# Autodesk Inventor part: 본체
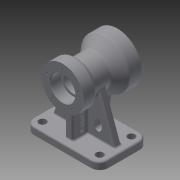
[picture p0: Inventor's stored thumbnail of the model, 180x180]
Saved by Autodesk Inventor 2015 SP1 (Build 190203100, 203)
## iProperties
Created: 2015-08
Part Number: 본체
Material: 일반
Document SubType Name: Modeling
Designer: jun
Density: 1 g/cm^3
Appearance: 기본값
Author: jun
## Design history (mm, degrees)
sketch "스케치1"
  geometry: L1 (-61, 40)-(61, 40); L2 (61, 40)-(61, -40); L3 (61, -40)-(-61, -40); L4 (-61, -40)-(-61, 40); L5 (-61, 40)-(61, -40); 2 further points
  constraints: 10 end point, 2 parallel, 1 coincident, 1 horizontal, 1 midpoint, 1 perpendicular
  dimensions: "d0" = 122 distance of L1.start L1.end; "d1" = 80 distance of L1.end L2.end
extrude "돌출1" new body sketch "스케치1" distance "d2" = 12; taper "d3" = 0 deg
sketch "스케치2"
  geometry: L1 (40, 12)-(40, 0) reference; L2 (40, 0)-(-40, 0) reference; L3 (-40, 0)-(-40, 12) reference; L4 (-40, 12)-(40, 12) reference; L5 (50, 90)-(-40, 90); L6 (50, 90)-(50, 49.861); L7 (50, 49.861)-(30, 49.861); L8 (-40, 90)-(-40, 55); L9 (-40, 55)-(-20, 55); L10 (30, 49.861)-(13.15, 64); L11 (13.15, 64)-(-14.804, 64); L12 (-14.804, 64)-(-20, 55); L13 (-40, 0)-(-40, 12) reference; 2 further points
  constraints: 16 end point, 2 horizontal, 2 perpendicular, 2 vertical, 1 midpoint, 1 vertical alignment
  dimensions: "d8" = 35 distance of L5.end L8.end; "d9" = 20 distance of L8.end L9.end; "d16" = 60 deg angle of L12 L11; "d103" = 90 distance of L5.start L5.end; "d106" = 90 distance between parallel lines of L2 L5; "d107" = 20 distance of L6.end L7.end; "d108" = 40 deg angle of L10 L11; "d109" = 26 distance between parallel lines of L5 L11; "d110" = 40.139 distance of L5.start L6.end
revolve "회전1" sketch "스케치2" stored, may be unused: angle "d17" = 90 deg
sketch "스케치3"
  geometry: L1 (61, 12)-(61, 0) reference; L2 (61, 0)-(-61, 0) reference; L3 (-61, 0)-(-61, 12) reference; L4 (-61, 12)-(61, 12) reference; L5 (-25.091, 83.185)-(-51, 12); L6 (-51, 12)-(51, 12); L7 (61, 12)-(-61, 12) reference; L8 (51, 12)-(25.091, 83.185); A1 r 26 centre (0, 90) between (-25.091, 83.185) and (25.091, 83.185) reference; A2 r 26 centre (0, 90) between (-25.091, 83.185) and (25.091, 83.185) reference; 1 further point
  constraints: 6 end point, 4 point on circle, 2 point on line
  dimensions: "d18" = 70 deg angle of L4 L8; "d19" = 70 deg angle of L4 L5; "d20" = 10 distance from line of L3 L5.end; "d21" = 10 distance from line of L1 L6.end
extrude "돌출2" join sketch "스케치3" stored distance "d22" = 12; taper "d23" = 0 deg
sketch "스케치4"
  geometry: L1 (40, 12)-(40, 0) reference; L2 (40, 0)-(-40, 0) reference; L3 (-40, 0)-(-40, 12) reference; L4 (-40, 12)-(-6, 12) reference; L5 (-6, 12)-(-6, 64) reference; L6 (-6, 64)-(-14.804, 64) reference; L7 (-14.804, 64)-(-20, 55) reference; L8 (-20, 55)-(-40, 55) reference; L9 (-40, 55)-(-40, 125) reference; L10 (-40, 125)-(-20, 125) reference; L11 (-20, 125)-(-14.804, 116) reference; L12 (-14.804, 116)-(13.15, 116) reference; L13 (13.15, 116)-(30, 130.139) reference; L14 (30, 130.139)-(50, 130.139) reference; L15 (50, 130.139)-(50, 49.861) reference; L16 (50, 49.861)-(30, 49.861) reference; L17 (30, 49.861)-(13.15, 64) reference; L18 (13.15, 64)-(6, 64) reference; L19 (6, 64)-(6, 12) reference; L20 (6, 12)-(40, 12) reference; L21 (-30, 55)-(-30, 12); L22 (36.676, 49.861)-(30, 12); L23 (40, 12)-(-40, 12) reference; 1 further point
  constraints: 4 end point, 3 point on line, 1 midpoint, 1 perpendicular
  dimensions: "d24" = 80 deg angle of L23 L22; "d25" = 10 distance from line of L22.end L1; "d26" = 10 distance between parallel lines of L3 L21
  node "절단 모서리 투영3"
feature "리브1" dims "d27" = 1, "d28" = 12, "d29" = 0, "d30" = 0, "d31" = 1, "d32" = 1
feature "리브2" dims "d33" = 1, "d34" = 12, "d35" = 0, "d36" = 0, "d37" = 1, "d38" = 1
sketch "스케치5"
  geometry: C1 r 40.139 at (0, 0) reference; C2 r 26 at (0, 0); 1 further point
  constraints: 1 centre point, 1 coincident
  dimensions: "d39" = 52 diameter of C2
extrude "돌출3" cut sketch "스케치5" distance "d40" = 20; taper "d41" = 0 deg
sketch "스케치6"
  geometry: L1 (-6, 39.688)-(-6, 78) reference; L2 (-6, 78)-(-61, 78) reference; L3 (-61, 78)-(-61, 90) reference; L4 (-61, 90)-(61, 90) reference; L5 (61, 90)-(61, 78) reference; L6 (61, 78)-(6, 78) reference; L7 (6, 78)-(6, 39.688) reference; L8 (6, 78)-(-6, 78) reference; C1 r 26 at (0, 0) reference; C2 r 19 at (0, 0); A1 r 40.139 centre (0, 0) between (-6, 39.688) and (6, 39.688) reference; 1 further point
  constraints: 1 centre point, 1 coincident
  dimensions: "d42" = 38 diameter of C2
extrude "돌출4" cut sketch "스케치6" distance "d43" = 3; taper "d44" = 0 deg
sketch "스케치7"
  geometry: L1 (-6, 78)-(-61, 78) reference; L2 (-61, 78)-(-61, 90) reference; L3 (-61, 90)-(61, 90) reference; L4 (61, 90)-(61, 78) reference; L5 (61, 78)-(6, 78) reference; L6 (6, 78)-(6, 37.14) reference; L7 (-6, 37.14)-(-6, 78) reference; C1 r 19 at (0, 0) reference; C2 r 16 at (0, 0); A1 r 37.622 centre (0, 0) between (-6, 37.14) and (6, 37.14) reference; 1 further point
  constraints: 1 centre point, 1 coincident
  dimensions: "d45" = 32 diameter of C2
extrude "돌출5" cut sketch "스케치7" stored distance "d46" = 3; taper "d47" = 0 deg
sketch "스케치8"
  geometry: L1 (-61, -78)-(61, -78) reference; L2 (61, -78)-(61, -90) reference; L3 (61, -90)-(-61, -90) reference; L4 (-61, -90)-(-61, -78) reference; C1 r 16 at (0, 0) reference; C2 r 35 at (0, 0) reference; C3 r 20 at (0, 0); 1 further point
  constraints: 1 centre point, 1 coincident
  dimensions: "d48" = 40 diameter of C3
extrude "돌출6" cut sketch "스케치8" distance "d49" = 17; taper "d50" = 0 deg
sketch "스케치9"
  geometry: C1 r 26 at (0, 0) reference; C2 r 40.139 at (0, 0) reference; 2 further points
  constraints: 1 vertical alignment
  dimensions: "d51" = 33 distance of C1.centre point (0, -33)
hole "구멍1" sketch "스케치9" at (0, -33) diameter "d52" = 3.242; stored, may be unused: countersink angle "d56" = 90 deg, drill point angle "d58" = 118 deg; dims "d53" = 8, "d54" = 4, "d55" = 2, "d57" = 13
sketch "스케치10"
  geometry: L1 (-61, -78)-(61, -78) reference; L2 (61, -78)-(61, -90) reference; L3 (61, -90)-(-61, -90) reference; L4 (-61, -90)-(-61, -78) reference; C1 r 20 at (0, 0) reference; C2 r 35 at (0, 0) reference; 2 further points
  constraints: 1 vertical alignment
  dimensions: "d62" = 27 distance of C1.centre point (0, 27)
hole "구멍2" sketch "스케치10" at (0, 27) diameter "d63" = 3.242; stored, may be unused: countersink angle "d67" = 90 deg, drill point angle "d69" = 118 deg; dims "d64" = 8, "d65" = 4, "d66" = 2, "d68" = 13
sketch "스케치11"
  geometry: L1 (-6, -64.702)-(-6, -12) reference; L2 (-6, -12)-(-51, -12) reference; L3 (-25.091, -83.185)-(-51, -12) reference; L4 (6, -12)-(6, -64.702) reference; L5 (51, -12)-(6, -12) reference; L6 (61, -12)-(51, -12) reference; L7 (61, 0)-(61, -12) reference; L8 (-61, 0)-(61, 0) reference; L9 (-61, -12)-(-61, 0) reference; L10 (-51, -12)-(-61, -12) reference; L11 (51, -12)-(25.091, -83.185) reference; L12 (24, -42)-(24, -24); L13 (30, -36)-(30, -30); L14 (18, -30)-(18, -36); L15 (0, 0)-(0, -64.702); C1 r 16 at (0, -90) reference; A1 r 26 centre (0, -90) between (25.091, -83.185) and (6, -64.702) reference; A2 r 26 centre (0, -90) between (-25.091, -83.185) and (25.091, -83.185) reference; A3 r 26 centre (0, -90) between (-6, -64.702) and (-25.091, -83.185) reference; A4 r 6 centre (24, -36) between (18, -36) and (30, -36); A5 r 6 centre (24, -30) between (30, -30) and (18, -30)
  constraints: 10 end point, 6 point on circle, 4 tangent, 2 centre point, 2 point on line, 2 vertical, 1 parallel
  dimensions: "d73" = 18 distance from line of A5.centre L5; "d74" = 18 distance of L12.end L12.start; "d75" = 12 distance of L14.end L13.start; "d76" = 24 distance from line of L15 A5.centre
extrude "돌출7" cut sketch "스케치11" stored distance "d77" = 17; taper "d78" = 0 deg
fillet "모깎기1" dims "d79" = 14
fillet "모깎기2" dims "d80" = 3
sketch "스케치12"
  geometry: L1 (-47, -37)-(47, -37) reference; L2 (58, -26)-(58, 26) reference; L3 (47, 37)-(-47, 37) reference; L4 (-58, 26)-(-58, -26) reference; L5 (-6, 30)-(6, 30) reference; L6 (6, 30)-(6, 6) reference; L7 (6, 6)-(51, 6) reference; L8 (51, 6)-(51, -6) reference; L9 (51, -6)-(6, -6) reference; L10 (6, -6)-(6, -30) reference; L11 (6, -30)-(-6, -30) reference; L12 (-6, -30)-(-6, -6) reference; L13 (-6, -6)-(-51, -6) reference; L14 (-51, -6)-(-51, 6) reference; L15 (-51, 6)-(-6, 6) reference; L16 (-6, 6)-(-6, 30) reference; C1 r 6 at (47, 26); C2 r 6 at (47, -26); C3 r 6 at (-47, -26); C4 r 6 at (-47, 26); A1 r 11 centre (47, -26) between (47, -37) and (58, -26) reference; A2 r 11 centre (47, 26) between (58, 26) and (47, 37) reference; A3 r 11 centre (-47, 26) between (-47, 37) and (-58, 26) reference; A4 r 11 centre (-47, -26) between (-58, -26) and (-47, -37) reference; 1 further point
  constraints: 4 centre point, 4 coincident
  dimensions: "d81" = 12 diameter of C1; "d82" = 12 diameter of C2; "d83" = 12 diameter of C3; "d84" = 12 diameter of C4
extrude "돌출8" cut sketch "스케치12" stored distance "d85" = 17; taper "d86" = 0 deg
fillet "모깎기3" dims "d87" = 3
fillet "모깎기4" dims "d88" = 3
fillet "모깎기5" dims "d89" = 3
fillet "모깎기6" dims "d90" = 3
fillet "모깎기7" dims "d91" = 5
fillet "모깎기8" dims "d92" = 5
fillet "모깎기9" dims "d93" = 0.3
fillet "모깎기10" dims "d94" = 3
chamfer "모따기1" distance "d95" = 1; stored, may be unused: second distance "d96" = 2, angle "d97" = 45 deg
sketch "스케치13"
  geometry: L1 (3, -10)-(3, 1) reference; L2 (-37.119, -3)-(0, -3) reference; 2 further points
  constraints: 1 other
  dimensions: "d98" = 24 distance from line of point (-21, 13) L1; "d99" = 16 distance from line of L2 point (-21, 13)
feature "엠보싱1" sketch "스케치13" dims "d0" = 122, "d1" = 80, "d100" = 0.5, "d101" = 0
node "솔리드1"
pattern_circular "원형 패턴1" dims angle "d60" = 360 deg
pattern_circular "원형 패턴2" dims angle "d71" = 360 deg
mirror "대칭1"
node "절단 모서리 투영1"
node "절단 모서리 투영2"
node "절단 모서리 투영4"
node "절단 모서리 투영5"
node "절단 모서리 투영6"
node "절단 모서리 투영7"
node "절단 모서리 투영8"
node "절단 모서리 투영9"
node "절단 모서리 투영10"
node "절단 모서리 투영11"
